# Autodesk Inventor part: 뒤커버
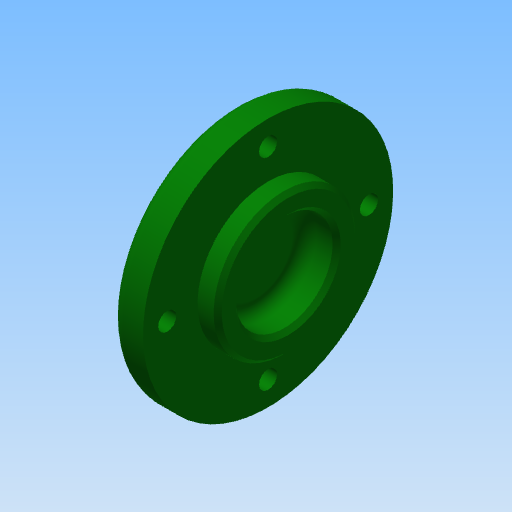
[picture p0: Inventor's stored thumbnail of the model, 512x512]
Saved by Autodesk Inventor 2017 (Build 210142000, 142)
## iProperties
Created: 2015-12
Part Number: 뒤커버
Document SubType Name: Modeling
Designer: mdu
Density: 2.71 g/cm^3
Material: 알루미늄 6061
Mass: 72.2029 g
Surface Area: 89.0628 cm^2
Volume: 26.6431 cm^3
Appearance: 진녹색
Author: mdu
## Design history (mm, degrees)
sketch "스케치1"
  geometry: L1 (-8, 0)-(8, 0); L2 (-8, 0)-(-8, 15.5); L3 (-8, 15.5)-(-5, 18.5); L4 (-5, 18.5)-(-5, 31); L5 (-5, 31)-(3, 31); L6 (3, 31)-(3, 17.5); L7 (3, 17.5)-(8, 17.5); L8 (8, 17.5)-(8, 0); 2 further points
  constraints: 16 end point, 4 parallel, 2 perpendicular, 1 coincident, 1 horizontal, 1 midpoint
  dimensions: "d0" = 16 distance of L1.start L1.end; "d1" = 62 diameter of L5 L1; "d2" = 35 diameter of L7 L1; "d3" = 37 diameter of L3.end L1; "d5" = 8 distance of L4.end L5.end; "d34" = 135 deg angle of L4 L3; "d36" = 5 distance of L6.end L7.end
revolve "회전1" sketch "스케치1" stored, may be unused: angle "d6" = 90 deg
sketch "스케치2" dims "d32" = 50
  geometry: 3 further points
  constraints: 2 vertical alignment, 1 coincident, 2 other
hole "구멍1" sketch "스케치2" at (0, 25) diameter "d8" = 4.5; stored, may be unused: countersink angle "d12" = 90 deg, drill point angle "d14" = 118 deg; dims "d9" = 6, "d10" = 8, "d11" = 4.4, "d13" = 8
hole "구멍2" diameter "d20" = 24; stored, may be unused: countersink angle "d24" = 90 deg, drill point angle "d26" = 0 deg; dims "d18" = 10, "d19" = 10, "d21" = 6, "d22" = 8, "d23" = 4.4, "d25" = 8
fillet "모깎기1" dims "d27" = 3
fillet "모깎기2" dims "d28" = 3
chamfer "모따기1" distance "d29" = 1; stored, may be unused: second distance "d30" = 2, angle "d31" = 45 deg
node "솔리드1"
pattern_circular "원형 패턴1" dims angle "d16" = 360 deg
